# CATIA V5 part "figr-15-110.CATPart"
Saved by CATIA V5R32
Part number: Part1
Bounding box of the stored display mesh (mm): x 0.737 to 206.429, y 0 to 112.04, z -1 to 2
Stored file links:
  D:\PROJECTS\Project 2022\CATIA V5 6R 2022\Resources\Part Files\c15_catia_v5_6r2022_prt\figr-15-110.CATPart
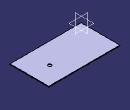
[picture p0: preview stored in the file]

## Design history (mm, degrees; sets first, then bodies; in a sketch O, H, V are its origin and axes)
SheetMetalParameters1: Thickness 2, BendRadius 4, KFactor 0.400515 {= log(min(100,max(20*SheetMetalParameters1.BendRadius,SheetMetalParameters1.Thickness)/SheetMetalParameters1.Thickness))/log(100)/2}, ReliefRadialLength 1, ReliefAxialLength 2, MinimumBendRadius 0
Body1 (main body)
  Sketch1 on xy-plane, origin (0, 0, 0), H (1, 0, 0), V (0, 1, 0)
    line L1 (0.7372, 112.0403) -> (206.4285, 112.0403)
    line L2 (206.4285, 112.0403) -> (206.4285, 0)
    line L3 (206.4285, 0) -> (0.7372, 0)
    line L4 (0.7372, 0) -> (0.7372, 112.0403)
    horizontal: L1 H, L3 H
    vertical: L2 V, L4 V
  Wall1: Thickness 2, Profile Sketch1, OffsetValue 0
  Sketch2 on face of Wall1, origin (152.409, 60.7083, 2), H (1, 0, 0), V (0, 1, 0)
    point P1 (0, 0)
  d_Stamp1: KFacteur 0.400515 {= SheetMetalParameters1.KFactor}, NewRoot_AttribNormalisation "No Standard", Stamp_FilletActivity false, Stamp_FilletRadius 2, Stamp_IntersectFilletRadius 2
